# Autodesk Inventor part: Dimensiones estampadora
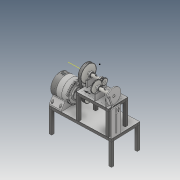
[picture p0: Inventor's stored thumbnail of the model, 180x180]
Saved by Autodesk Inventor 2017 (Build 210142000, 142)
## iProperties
Created: 2019-03
Part Number: Dimensiones estampadora
Material: Generic
Document SubType Name: Modeling
Designer: user
Density: 1 g/cm^3
Appearance: Default
Author: user
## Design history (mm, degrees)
derived "Prueba parcial 1.iam"
body "Solid1"
node "Marco grande.iam:1::Frame0001.iam:1::Skeleton0001.ipt:1"
node "Marco grande.iam:1::Frame0001.iam:1::ANSI 1x1 00000001:1"
node "Marco grande.iam:1::Frame0001.iam:1::ANSI 1x1 00000002:1"
node "Marco grande.iam:1::Frame0001.iam:1::ANSI 1x1 00000003:1"
node "Marco grande.iam:1::Frame0001.iam:1::ANSI 1x1 00000004:1"
node "Marco grande.iam:1::Frame0001.iam:1::ANSI 1x1 00000005:1"
node "Marco grande.iam:1::Frame0001.iam:1::ANSI 1x1 00000006:1"
node "Marco grande.iam:1::Frame0001.iam:1::ANSI 1x1 00000007:1"
node "Marco grande.iam:1::Frame0001.iam:1::ANSI 1x1 00000008:1"
node "Placa base.ipt:1"
node "Ensamble motor 2.iam:1::Base motor.ipt:1"
sketch "Sketch2"
  geometry: 1 further point
node "Ensamble motor 2.iam:1::Motenergy ME1003.ipt:1"
node "Marco pequeño.iam:1::Frame0001.iam:1::Skeleton0001.ipt:1"
node "Marco pequeño.iam:1::Frame0001.iam:1::ANSI 1x1 00000001:1"
node "Marco pequeño.iam:1::Frame0001.iam:1::ANSI 1x1 00000002:1"
node "Marco pequeño.iam:1::Frame0001.iam:1::ANSI 1x1 00000003:1"
node "Marco pequeño.iam:1::Frame0001.iam:1::ANSI 1x1 00000004:1"
node "Marco pequeño.iam:1::Frame0001.iam:1::ANSI 1x1 00000005:1"
node "Marco pequeño.iam:1::Frame0001.iam:1::ANSI 1x1 00000006:1"
node "Marco pequeño.iam:1::Frame0001.iam:1::ANSI 1x1 00000007:1"
node "Marco pequeño.iam:1::Frame0001.iam:1::ANSI 1x1 00000008:1"
node "Placa base ejes.ipt:1"
node "Soporte chumaceras.ipt:1"
node "Soporte chumaceras.ipt:2"
node "Soporte chumaceras.ipt:3"
node "Soporte chumaceras.ipt:4"
node "Ensamble chumacera.iam:1::Base chumacera.ipt:1"
node "Ensamble chumacera.iam:2::Base chumacera.ipt:1"
node "Ensamble chumacera.iam:3::Base chumacera.ipt:1"
node "Ensamble chumacera.iam:4::Base chumacera.ipt:1"
node "Shaft:1::Shaft:1"
node "Shaft:2::Shaft:1"
node "Spur Gears:1::Spur Gear1:1"
node "Spur Gears:1::Spur Gear2:1"
node "Synchronous Belts Transmission:1::Synchronous Belt:1"
workaxis "Work Axis1"
workaxis "Work Axis2"
node "Synchronous Belts Transmission:1::Synchronous Pulley1:1"
node "Synchronous Belts Transmission:1::Synchronous Pulley2:1"
node "Part12.ipt:1"
node "Rueda.ipt:1"
sketch "Sketch2_1"
  geometry: 1 further point
node "Part13.ipt:1"
other parameters: "G_L_9" = 204.737 [user parameter], "G_L_10" = 204.737 [user parameter]
